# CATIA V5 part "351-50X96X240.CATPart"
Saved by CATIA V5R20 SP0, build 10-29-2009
Part number: 351-50X96X240
Definition: NONE
Nomenclature: 351-50X96X240
Source: Unknown
Description: 351-50X96X240
Bounding box of the stored display mesh (mm): x -10 to 230, y -32.5 to 32.5, z -32.5 to 32.5
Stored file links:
  C:\Users\Utente\Desktop\IO LAVORO\3D X SITO CF\X SITO\PLASTICA\351\351-50X96X240.CATPart
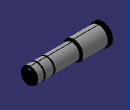
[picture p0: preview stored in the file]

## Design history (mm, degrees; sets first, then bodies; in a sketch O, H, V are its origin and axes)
Body1 "351-50X96X240" (main body)
  Solid1: solid without history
